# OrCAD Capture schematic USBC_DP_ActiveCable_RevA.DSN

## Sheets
1 P1_RevisionNote: title: Type-C to DP Active Cable Board; rev: A.0; company: Texas Instruments, CIS/ICP
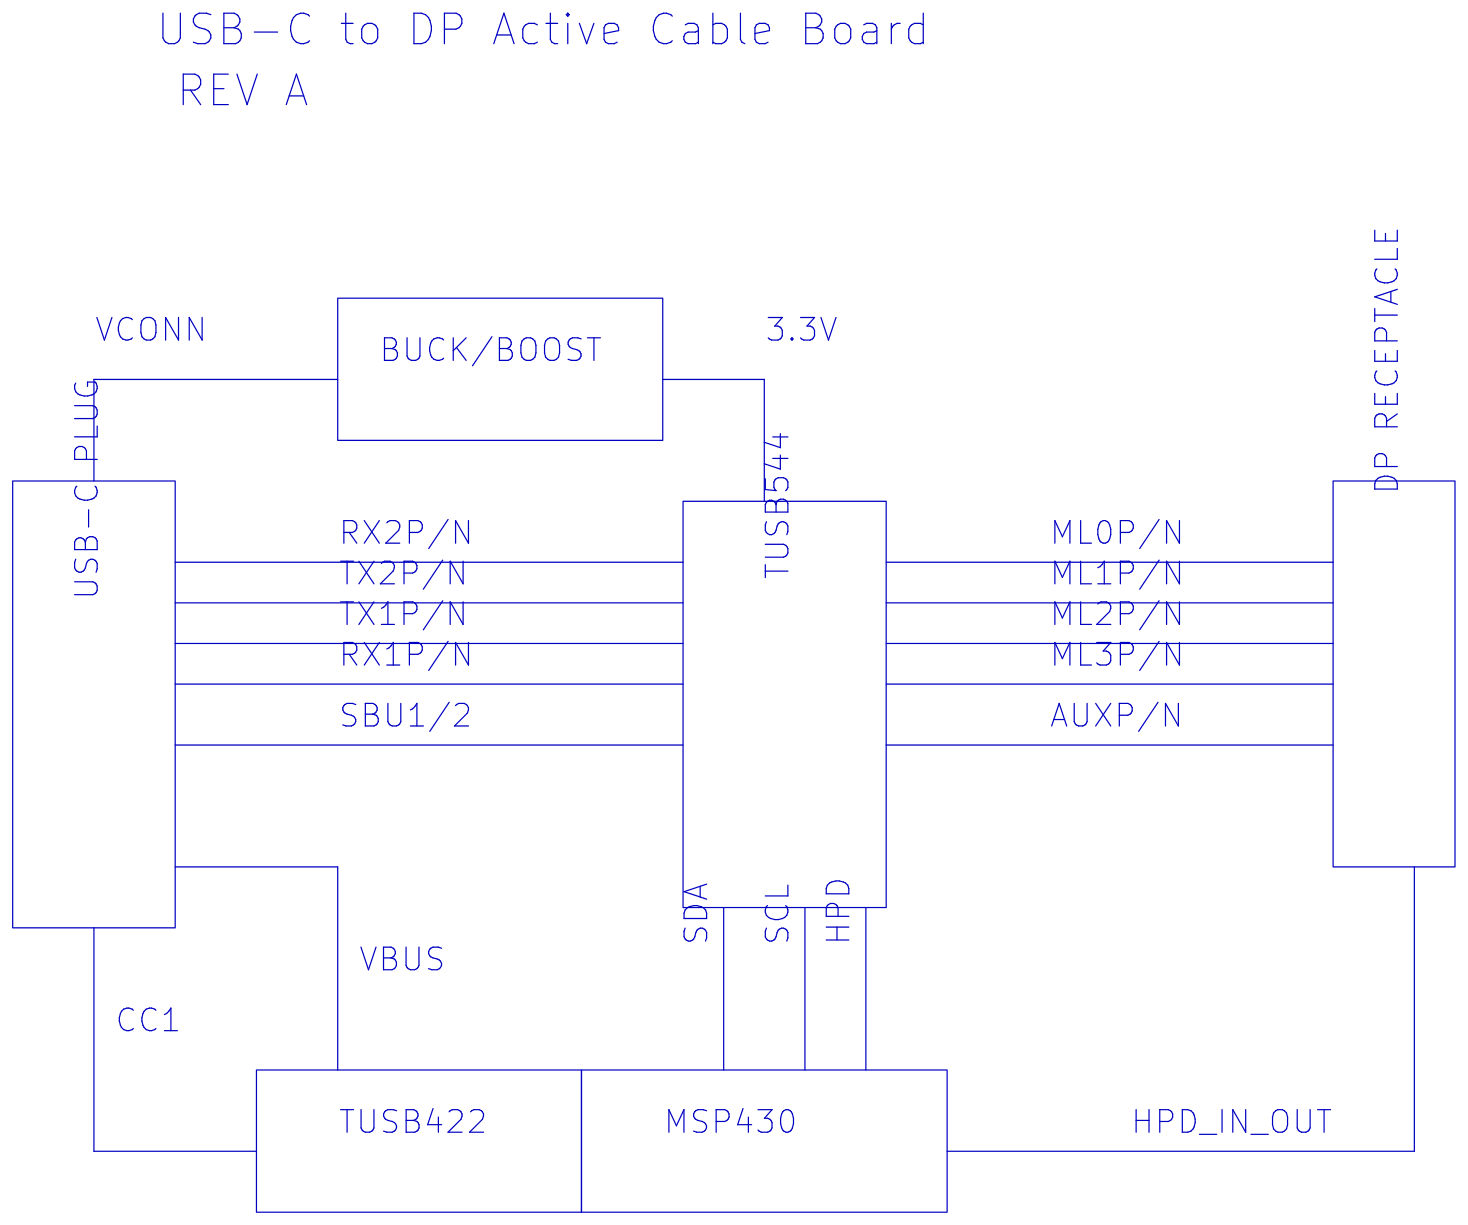
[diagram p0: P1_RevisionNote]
2 P2_TypeC_DP_Connectors: size C; title: USB-C DP ActiveCable Board: USB Connectors
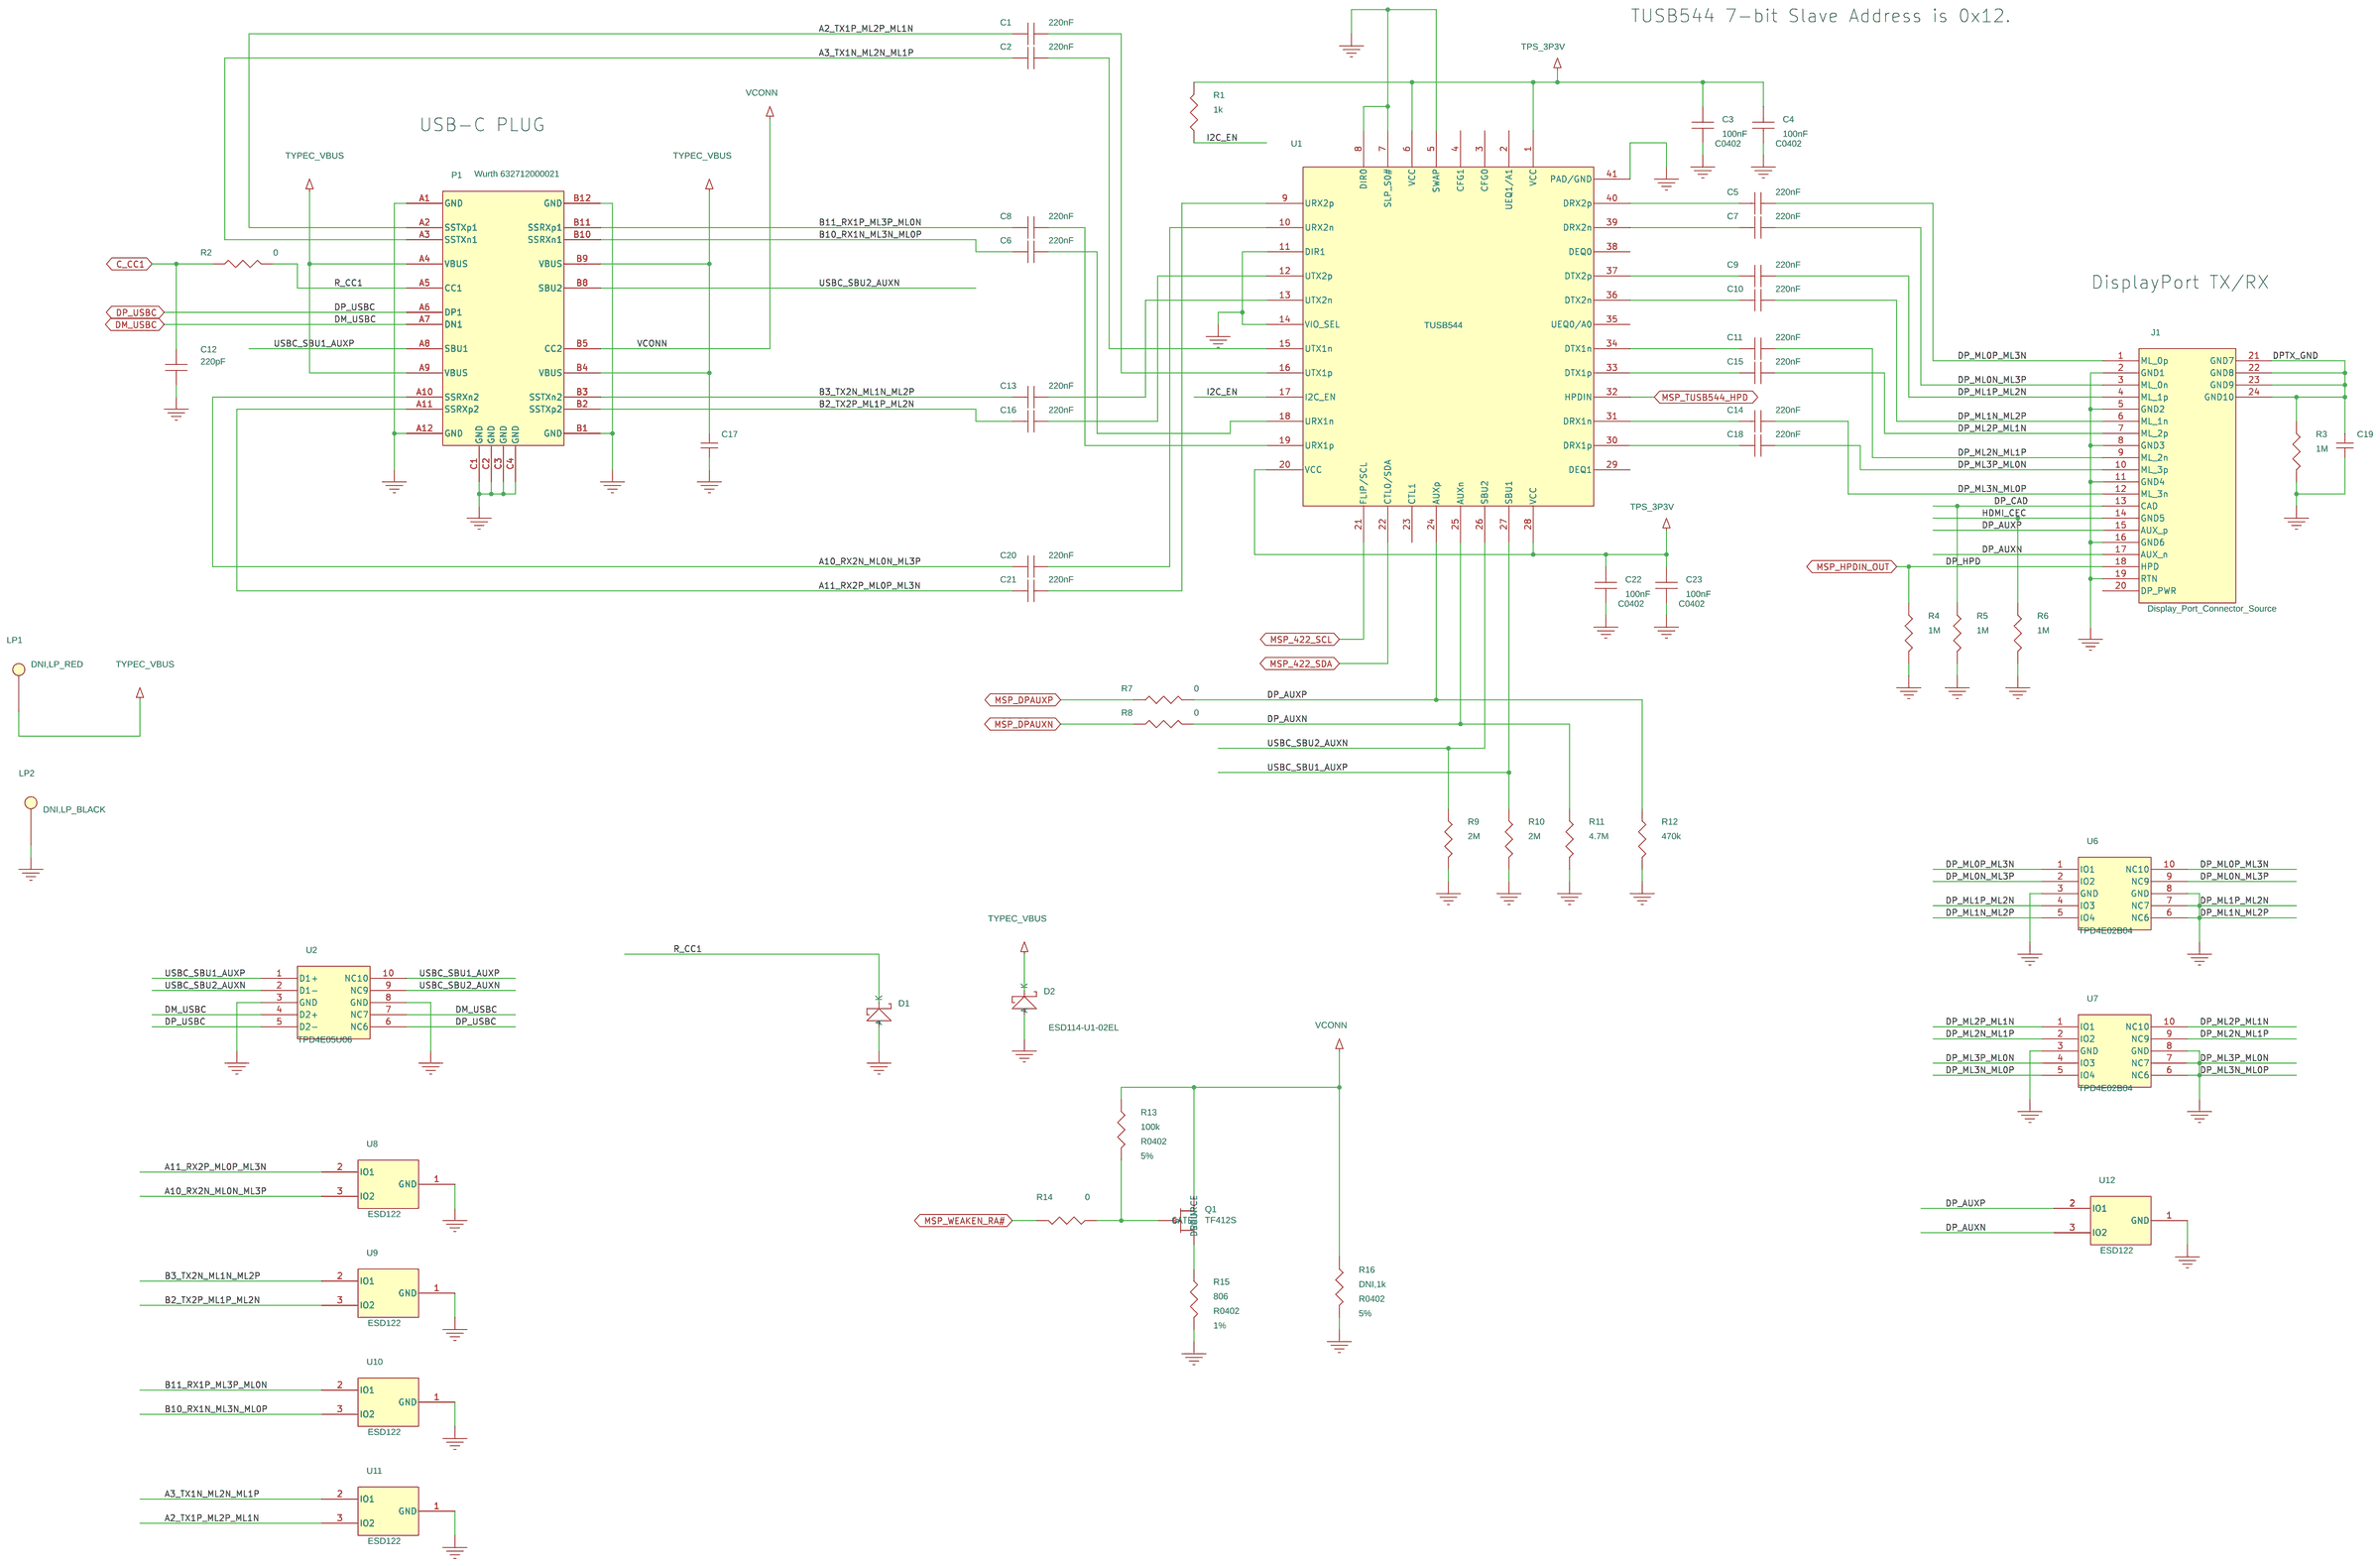
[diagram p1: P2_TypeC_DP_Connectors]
3 P3_TUSB422: size A; title: USB-C DP Active Cable Board: TUSB422
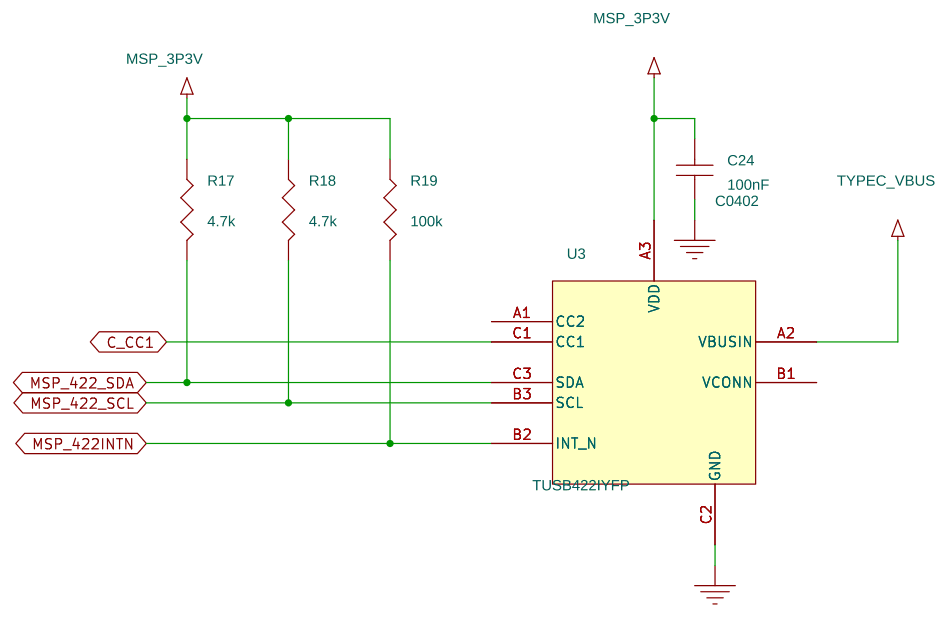
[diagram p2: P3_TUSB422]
4 P4_MSP430: size B; title: USB-C DP Active Cable Board: MSP430F5528
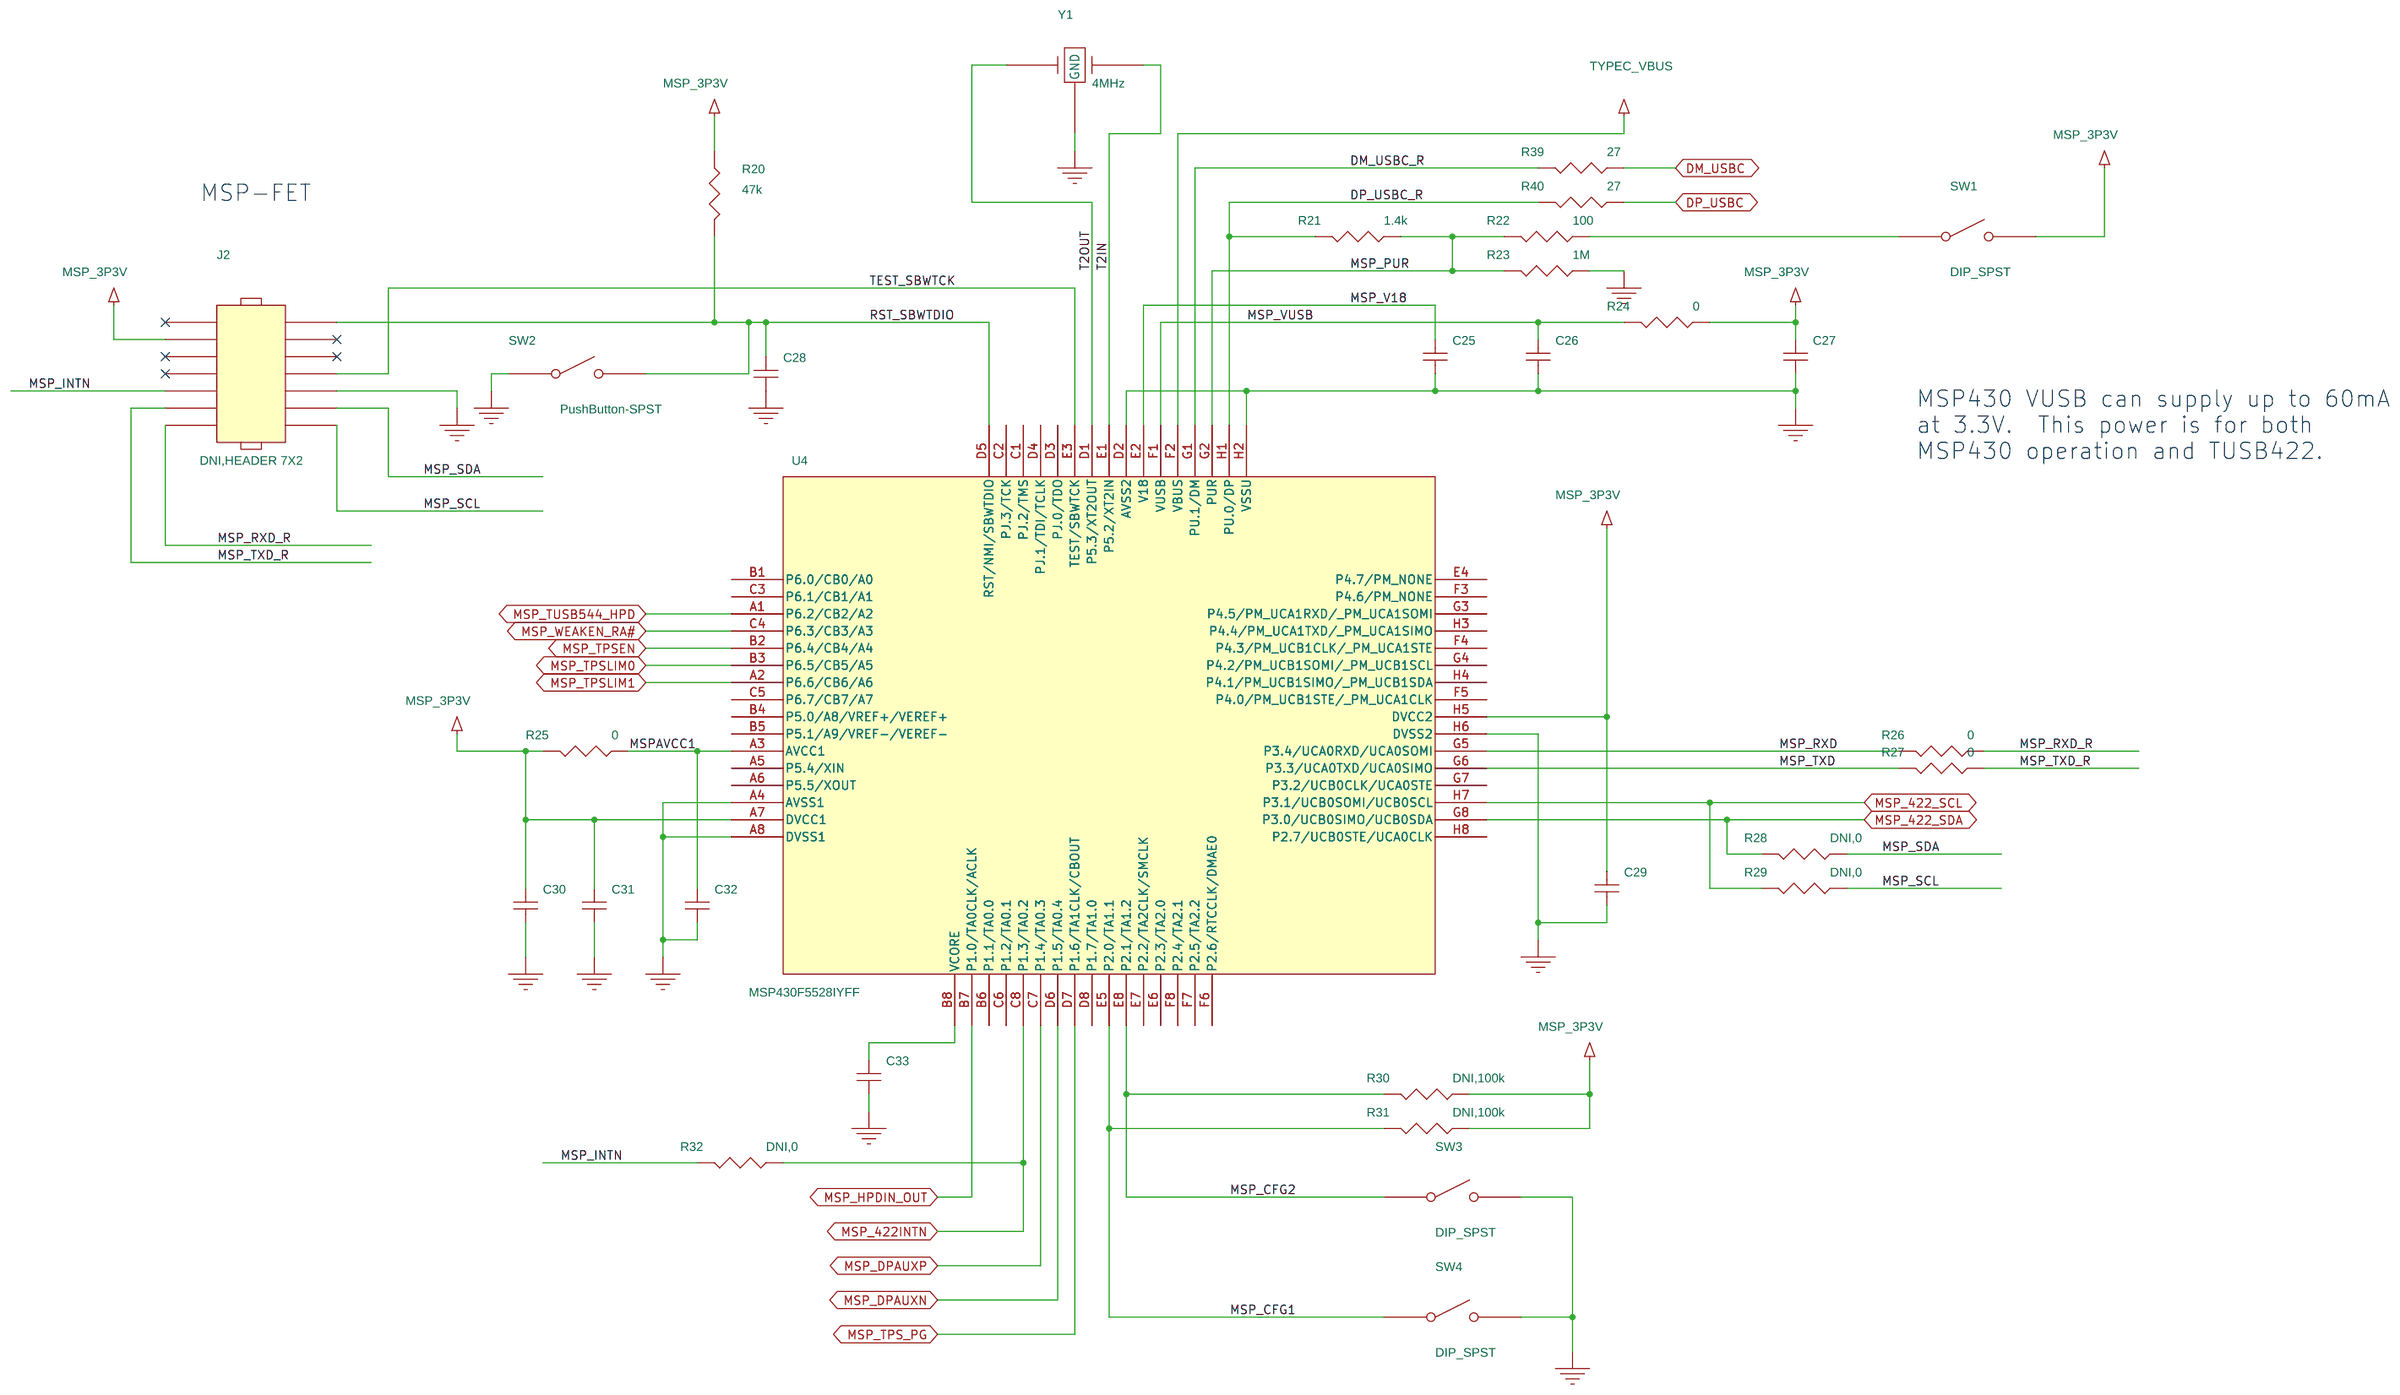
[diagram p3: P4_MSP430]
5 P5_POWER: size A; title: USB-C DP Active Cable Board: TPS63051
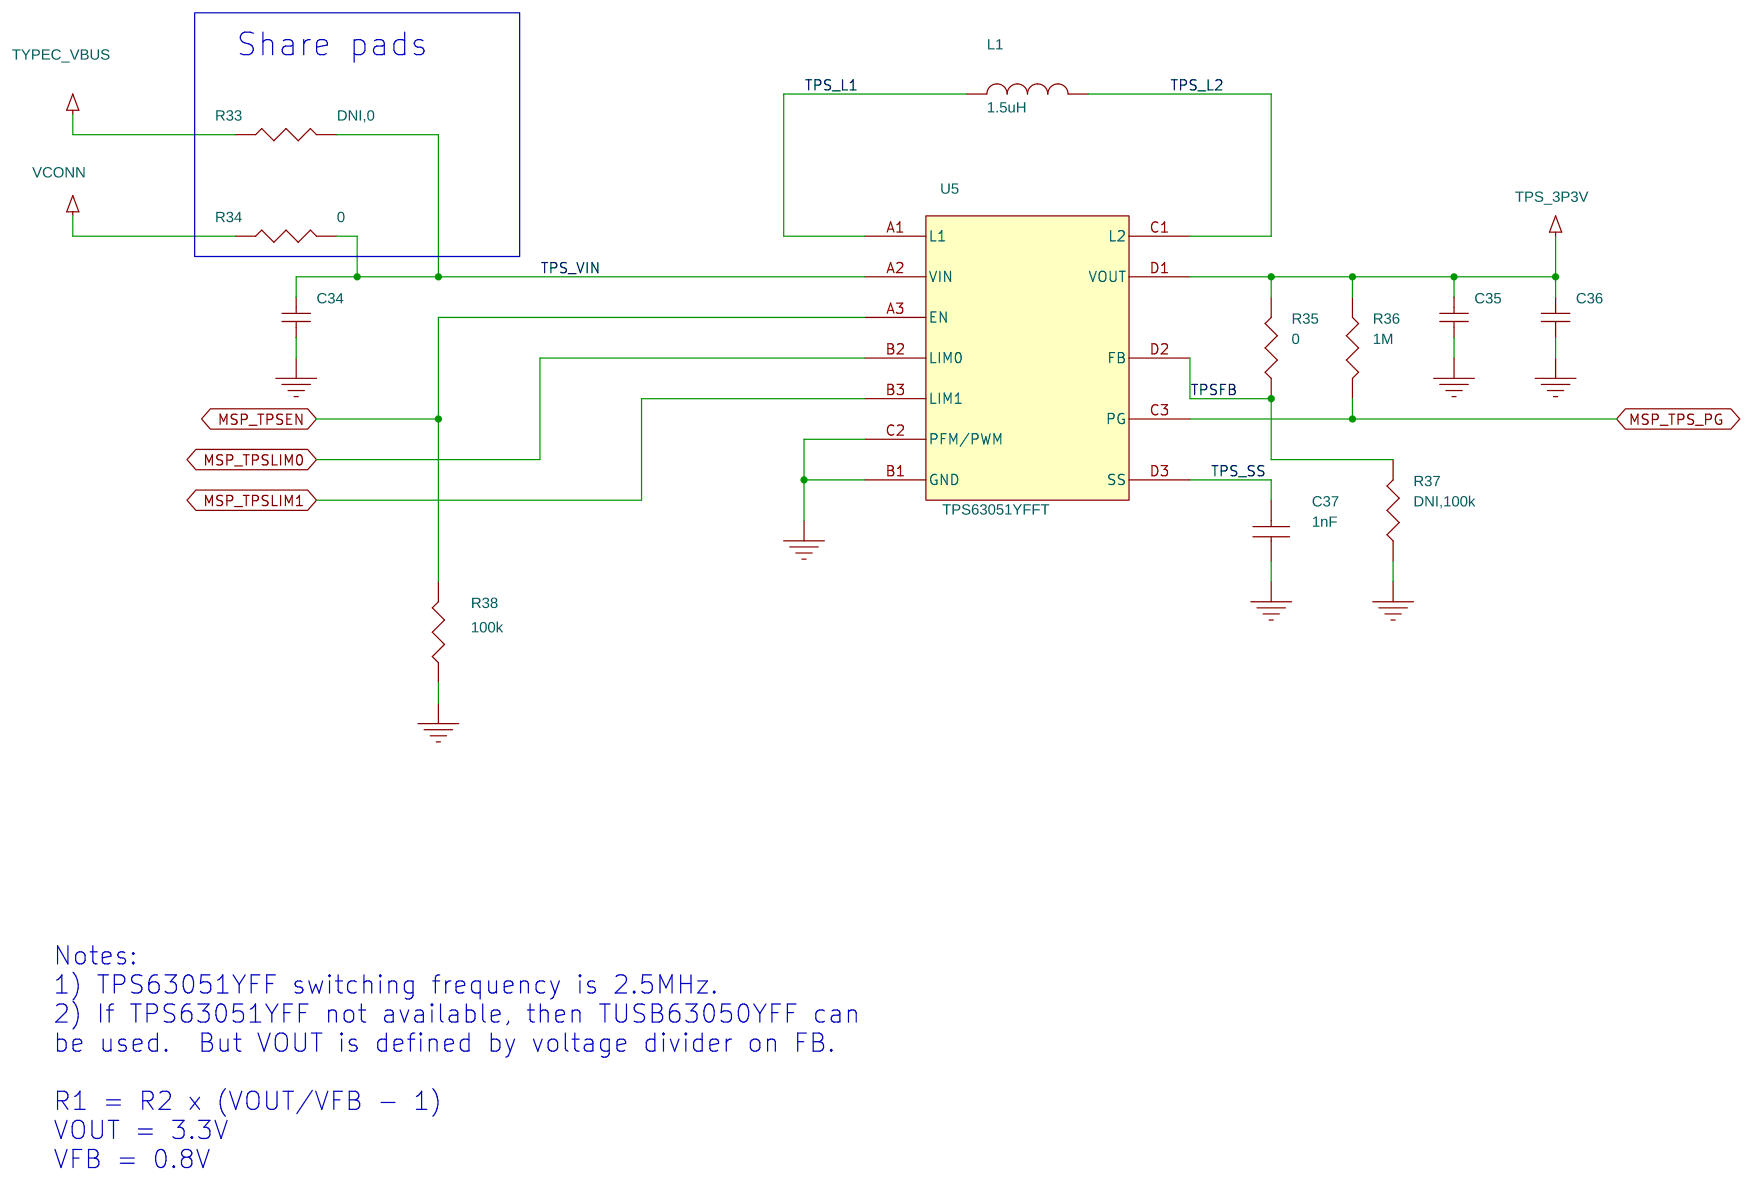
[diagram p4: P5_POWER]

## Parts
sheet P2_TypeC_DP_Connectors
C1  220nF  [C0402]
C2  220nF  [C0402]
C3  100nF  [C0402]
C4  100nF  [C0402]
C5  220nF  [C0402]
C6  220nF  [C0402]
C7  220nF  [C0402]
C8  220nF  [C0402]
C9  220nF  [C0402]
C10  220nF  [C0402]
C11  220nF  [C0402]
C12  220pF  [C0402]
C13  220nF  [C0402]
C14  220nF  [C0402]
C15  220nF  [C0402]
C16  220nF  [C0402]
C17  4.7uF  [C0402]
C18  220nF  [C0402]
C19  1uF  [C0402]
C20  220nF  [C0402]
C21  220nF  [C0402]
C22  100nF  [C0402]
C23  100nF  [C0402]
D1  TPD1E05U06  [DPY0002AA]
D2  ESD114-U1-02EL  [sod_882]
J1  Display_Port_Connector_Source  [CON_DP_SD-47272-001]
LP1  DNI,LP_RED  [tp_thvt_060_rnd]
LP2  DNI,LP_BLACK  [tp_thvt_060_rnd]
P1  Wurth 632712000021  [USB-C_SMRT_632_712_000_021]
Q1  TF412S  [SOT-883]
R1  1k  [R0402]
R2  0  [R0402]
R3  1M  [R0402]
R4  1M  [R0402]
R5  1M  [R0402]
R6  1M  [R0402]
R7  0  [R0402]
R8  0  [R0402]
R9  2M  [R0402]
R10  2M  [R0402]
R11  4.7M  [R0402]
R12  470k  [R0402]
R13  100k  [R0402]
R14  0  [R0402]
R15  806  [R0402]
R16  DNI,1k  [R0402]
U1  TUSB544  [RNQ0040A]
U2  TPD4E05U06  [DQA0010A]
U6  TPD4E02B04  [DQA]
U7  TPD4E02B04  [DQA]
U8  ESD122  [DMX0003A]
U9  ESD122  [DMX0003A]
U10  ESD122  [DMX0003A]
U11  ESD122  [DMX0003A]
U12  ESD122  [DMX0003A]
sheet P3_TUSB422
C24  100nF  [C0402]
R17  4.7k  [R0402]
R18  4.7k  [R0402]
R19  100k  [R0402]
U3  TUSB422IYFP  [YFP_BGA_9]
sheet P4_MSP430
C25  220nF  [C0402]
C26  220nF  [C0402]
C27  1uF  [C0402]
C28  1nF  [C0402]
C29  100nF  [C0402]
C30  1uF  [C0402]
C31  100nF  [C0402]
C32  100nF  [C0402]
C33  470nF  [C0402]
J2  DNI,HEADER 7X2  [HDR_THVT_2x7_100_M]
R20  47k  [R0402]
R21  1.4k  [R0402]
R22  100  [R0402]
R23  1M  [R0402]
R24  0  [R0402]
R25  0  [R0402]
R26  0  [R0402]
R27  0  [R0402]
R28  DNI,0  [R0402]
R29  DNI,0  [R0402]
R30  DNI,100k  [R0402]
R31  DNI,100k  [R0402]
R32  DNI,0  [R0402]
R39  27  [R0402]
R40  27  [R0402]
SW1  DIP_SPST  [SW_SMVT_CHS-01TA]
SW2  PushButton-SPST  [SW_SMVT_KXT]
SW3  DIP_SPST  [SW_SMVT_CHS-01TA]
SW4  DIP_SPST  [SW_SMVT_CHS-01TA]
U4  MSP430F5528IYFF  [YFF0064A]
Y1  4MHz  [XTAL_SM_3_CSTCR_G15L]
sheet P5_POWER
C34  10uF  [C0603]
C35  10uF  [C0402]
C36  10uF  [C0402]
C37  1nF  [C0402]
L1  1.5uH  [IND_DFE2016C]
R33  DNI,0  [R0603]
R34  0  [R0603]
R35  0  [R0402]
R36  1M  [R0402]
R37  DNI,100k  [R0402]
R38  100k  [R0402]
U5  TPS63051YFFT  [YFF0012A]

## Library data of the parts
C1 C2 C5-C16 C18 C20 C21 C37 = cc0402: 6.3V
C3 C4 C22-C24 = CAP_NP: 10V Capacitor
C17 C19 C25-C36 = CAP: 10V Capacitor; $SEC: 1; ATIPartNo: 4170010400G; CDS_LIB: capacitor; DRAWING: @LIGHTNING_BOLT_NB_LIB.NOTE_BOOK(SCH_1):PAGE1; PHYS_PAGE: 1; ROT: 0; TOLERANCE: 10%; VER: 1; VOLTAGE: 10V; XY: (-8750,4250)
D1 = TPD1E05U06
D2 = TPD1E05U06: Manuf: Infineon Tech; Manuf PN: ESD114U102ELE6327XTMA1
J1 = Display_Port_Connector_Source_0: Manuf: Molex; Manuf PN: 47272-0001
LP1 = TESTLOOP: Manufacturer: KOBIKONN; Manufacturer Part Number: 151-107-RC
LP2 = TESTLOOP: Manufacturer: KOBIKONN; Manufacturer Part Number: 151-105-RC
P1 = Type_C_Plug_0: Manuf: Wurth Electronics; Manuf PN: 632712000021; Manufacturer: Wurth Electronics; Manufacturer Part Number: 632712000021
Q1 = TF412S
R1 R13 R14 R16 = R: Resistor; Tolerance: 5%
R2 R7 R8 R33-R35 R37 R38 = R: Tolerance: 5%
R3-R6 R9-R12 R17-R32 R36 R39 R40 = R_2: Resistor; Tolerance: 5%
R15 = R: Resistor; Tolerance: 1%
U1 = TUSB1044RNQ: Manuf: Texas Instruments; Manuf PN: TUSB544RNQR
U2 = TPD4E05U06: Manuf: Texas Instruments
U6 U7 = TPD4E02B04: Manuf PN: TPD4E02B04DQAR
U8-U12 = ESD122
U3 = TUSB422_WCSP: Manuf: Texas Instruments; Manuf PN: TUSB422IYFPT; Manufacturer Part Number: TUSB422IYFPT
J2 = HEADER_7X2: Header; Manuf: Amphenol FCI; Manuf PN: 67996-114HLF; TI_SILKSCREEN: MSP430_SERIAL_WIRE
SW1 SW3 SW4 = SW_MAG-SPST: Manuf: Copal Electronics; Manuf PN: CHS-01TA
SW2 = SW_MAG-SPST: Manuf: C&K; Manuf PN: KXT 131 LHS
U4 = MSP430F5528IYFF_1: Manuf: Texas Instruments; Manuf PN: MSP430F5528IYFFR
Y1 = XM_SM_0: Manuf: Murata; Manuf PN: CSTCR4M00G15L99-R0
L1 = INDUCTOR: Inductor; CDS_LIB: Inductor; Manuf: TOKO; Manuf PN: 1286AS-H-1R5M; Manufacturer: TOKO; Manufacturer Part Number: 1286AS-H-1R5M; Manufacturer's Part Number: 1286AS-H-1R5M
U5 = TPS63051YFFT: Manuf: Texas Instruments

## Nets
GND: C3.1 C4.1 C12.1 C17.2(B) C19.2(B) C22.1 C23.1 C24.1 C25.2(B) C26.2(B) C27.2(B) C28.2(B) C29.2(B) C30.2(B) C31.2(B) C32.2(B) C33.2(B) C34.2(B) C35.2(B) C36.2(B) C37.1 D1.2(A) D2.2(A) J1.2(GND1) J1.5(GND2) J1.8(GND3) J1.11(GND4) J1.16(GND6) J1.19(RTN) J2.9 LP2.1 P1.A1(GND) P1.A12(GND) P1.B1(GND) P1.B12(GND) P1.C1(GND) P1.C2(GND) P1.C3(GND) P1.C4(GND) R3.2 R4.2 R5.2 R6.2 R9.2 R10.2 R11.2 R12.2 R15.2 R16.2 R23.1 R37.1 R38.1 SW2.1 SW3.2 SW4.2 U1.5(SWAP) U1.7(SLP_S0#) U1.8(DIR0) U1.11(DIR1) U1.14(VIO_SEL) U1.41(PAD/GND) U2.3(GND) U2.8(GND) U3.C2(GND) U4.A4(AVSS1) U4.A8(DVSS1) U4.D2(AVSS2) U4.H2(VSSU) U4.H6(DVSS2) U5.B1(GND) U5.C2(PFM/PWM) U6.3(GND) U6.8(GND) U7.3(GND) U7.8(GND) U8.1(GND) U9.1(GND) U10.1(GND) U11.1(GND) U12.1(GND) Y1.2(GND)
A2_TX1P_ML2P_ML1N: C1.2 P1.A2(SSTXp1) U11.3(IO2)
A3_TX1N_ML2N_ML1P: C2.2 P1.A3(SSTXn1) U11.2(IO1)
A10_RX2N_ML0N_ML3P: C20.2 P1.A10(SSRXn2) U8.3(IO2)
A11_RX2P_ML0P_ML3N: C21.2 P1.A11(SSRXp2) U8.2(IO1)
B2_TX2P_ML1P_ML2N: C16.2 P1.B2(SSTXp2) U9.3(IO2)
B3_TX2N_ML1N_ML2P: C13.2 P1.B3(SSTXn2) U9.2(IO1)
B10_RX1N_ML3N_ML0P: C6.2 P1.B10(SSRXn1) U10.3(IO2)
B11_RX1P_ML3P_ML0N: C8.2 P1.B11(SSRXp1) U10.2(IO1)
C_CC1: C12.2 R2.1 U3.C1(CC1)
DM_USBC: P1.A7(DN1) R39.1 U2.4(D2+) U2.7(NC7)
DM_USBC_R: R39.2 U4.G1(PU.1/DM)
DP_AUXN: J1.17(AUX_n) R8.2 R11.1 U1.25(AUXn) U12.3(IO2)
DP_AUXP: J1.15(AUX_p) R7.2 R12.1 U1.24(AUXp) U12.2(IO1)
DP_CAD: J1.13(CAD) R5.1
DP_ML0N_ML3P: C7.1 J1.3(ML_0n) U6.2(IO2) U6.9(NC9)
DP_ML0P_ML3N: C5.1 J1.1(ML_0p) U6.1(IO1) U6.10(NC10)
DP_ML1N_ML2P: C10.1 J1.6(ML_1n) U6.5(IO4) U6.6(NC6)
DP_ML1P_ML2N: C9.1 J1.4(ML_1p) U6.4(IO3) U6.7(NC7)
DP_ML2N_ML1P: C11.1 J1.9(ML_2n) U7.2(IO2) U7.9(NC9)
DP_ML2P_ML1N: C15.1 J1.7(ML_2p) U7.1(IO1) U7.10(NC10)
DP_ML3N_ML0P: C14.1 J1.12(ML_3n) U7.5(IO4) U7.6(NC6)
DP_ML3P_ML0N: C18.1 J1.10(ML_3p) U7.4(IO3) U7.7(NC7)
DP_USBC: P1.A6(DP1) R40.1 U2.5(D2-) U2.6(NC6)
DP_USBC_R: R21.2 R40.2 U4.H1(PU.0/DP)
DPTX_GND: C19.1(A) J1.21(GND7) J1.22(GND8) J1.23(GND9) J1.24(GND10) R3.1
HDMI_CEC: J1.14(GND5) R6.1
I2C_EN: R1.1 U1.17(I2C_EN)
MSP_3P3V: C24.2 C27.1(A) C29.1(A) C30.1(A) C31.1(A) J2.4 R17.1 R18.1 R19.1 R20.1 R24.1 R25.2 R30.1 R31.1 SW1.2 U3.A3(VDD) U4.A7(DVCC1) U4.H5(DVCC2)
MSP_422_SCL: R18.2 R29.2 U1.21(FLIP/SCL) U3.B3(SCL) U4.H7(P3.1/UCB0SOMI/UCB0SCL)
MSP_422_SDA: R17.2 R28.2 U1.22(CTL0/SDA) U3.C3(SDA) U4.G8(P3.0/UCB0SIMO/UCB0SDA)
MSP_422INTN: R19.2 R32.1 U3.B2(INT_N) U4.C8(P1.3/TA0.2)
MSP_CFG1: R31.2 SW4.1 U4.E5(P2.0/TA1.1)
MSP_CFG2: R30.2 SW3.1 U4.E8(P2.1/TA1.2)
MSP_DPAUXN: R8.1 U4.D6(P1.5/TA0.4)
MSP_DPAUXP: R7.1 U4.C7(P1.4/TA0.3)
MSP_HPDIN_OUT: J1.18(HPD) R4.1 U4.B7(P1.0/TA0CLK/ACLK)
MSP_INTN: J2.10 R32.2
MSP_PUR: R21.1 R22.2 R23.2 U4.G2(PUR)
MSP_RXD: R26.2 U4.G5(P3.4/UCA0RXD/UCA0SOMI)
MSP_RXD_R: J2.14 R26.1
MSP_SCL: J2.13 R29.1
MSP_SDA: J2.11 R28.1
MSP_TPS_PG: R36.2 U4.D7(P1.6/TA1CLK/CBOUT) U5.C3(PG)
MSP_TPSEN: R38.2 U4.B2(P6.4/CB4/A4) U5.A3(EN)
MSP_TPSLIM0: U4.B3(P6.5/CB5/A5) U5.B2(LIM0)
MSP_TPSLIM1: U4.A2(P6.6/CB6/A6) U5.B3(LIM1)
MSP_TUSB544_HPD: U1.32(HPDIN) U4.A1(P6.2/CB2/A2)
MSP_TXD: R27.2 U4.G6(P3.3/UCA0TXD/UCA0SIMO)
MSP_TXD_R: J2.12 R27.1
MSP_V18: C25.1(A) U4.E2(V18)
MSP_VUSB: C26.1(A) R24.2 U4.F1(VUSB)
MSP_WEAKEN_RA#: R14.1 U4.C4(P6.3/CB3/A3)
MSPAVCC1: C32.1(A) R25.1 U4.A3(AVCC1)
R_CC1: D1.1(K) P1.A5(CC1) R2.2
RST_SBWTDIO: C28.1(A) J2.1 R20.2 SW2.2 U4.D5(RST/NMI/SBWTDIO)
T2IN: U4.E1(P5.2/XT2IN) Y1.3
T2OUT: U4.D1(P5.3/XT2OUT) Y1.1
TEST_SBWTCK: J2.7 U4.E3(TEST/SBWTCK)
TPS_3P3V: C3.2 C4.2 C22.2 C23.2 C35.1(A) C36.1(A) R1.2 R35.2 R36.1 U1.1(VCC) U1.6(VCC) U1.20(VCC) U1.28(VCC) U5.D1(VOUT)
TPS_L1: L1.1 U5.A1(L1)
TPS_L2: L1.2 U5.C1(L2)
TPS_SS: C37.2 U5.D3(SS)
TPS_VIN: C34.1(A) R33.2 R34.2 U5.A2(VIN)
TPSFB: R35.1 R37.2 U5.D2(FB)
TypeC_VBUS: C17.1(A) D2.1(K) LP1.1 P1.A4(VBUS) P1.A9(VBUS) P1.B4(VBUS) P1.B9(VBUS) R33.1 U3.A2(VBUSIN) U4.F2(VBUS)
USBC_SBU1_AUXP: P1.A8(SBU1) R10.1 U1.27(SBU1) U2.1(D1+) U2.10(NC10)
USBC_SBU2_AUXN: P1.B8(SBU2) R9.1 U1.26(SBU2) U2.2(D1-) U2.9(NC9)
VCONN: P1.B5(CC2) Q1.2(DRAIN) R13.1 R16.1 R34.1
N17347753: C33.1(A) U4.B8(VCORE)
N17354680: R22.1 SW1.1
N17413185: C5.2 U1.40(DRX2p)
N17413188: C7.2 U1.39(DRX2n)
N17413191: C9.2 U1.37(DTX2p)
N17413194: C10.2 U1.36(DTX2n)
N17413197: C11.2 U1.34(DTX1n)
N17413200: C15.2 U1.33(DTX1p)
N17413203: C14.2 U1.31(DRX1n)
N17413206: C18.2 U1.30(DRX1p)
N17415406: C21.1 U1.9(URX2p)
N17415415: C20.1 U1.10(URX2n)
N17415424: C16.1 U1.12(UTX2p)
N17415436: C13.1 U1.13(UTX2n)
N17415457: C8.1 U1.19(URX1p)
N17415476: C6.1 U1.18(URX1n)
N17415496: C2.1 U1.15(UTX1n)
N17415505: C1.1 U1.16(UTX1p)
N17425671: Q1.3(GATE) R13.2 R14.2
N17429646: Q1.1(SOURCE) R15.1

Not connected (* = marked no-connect by the designer): J1 20(DP_PWR); J2 2* 3* 5* 6* 8*; U1 2(UEQ1/A1) 3(CFG0) 4(CFG1) 23(CTL1) 29(DEQ1) 35(UEQ0/A0) 38(DEQ0); U3 A1(CC2) B1(VCONN); U4 A5(P5.4/XIN) A6(P5.5/XOUT) B1(P6.0/CB0/A0) B4(P5.0/A8/VREF+/VEREF+) B5(P5.1/A9/VREF-/VEREF-) B6(P1.1/TA0.0) C1(PJ.2/TMS) C2(PJ.3/TCK) C3(P6.1/CB1/A1) C5(P6.7/CB7/A7) C6(P1.2/TA0.1) D3(PJ.0/TDO) D4(PJ.1/TDI/TCLK) D8(P1.7/TA1.0) E4(P4.7/PM_NONE) E6(P2.3/TA2.0) E7(P2.2/TA2CLK/SMCLK) F3(P4.6/PM_NONE) F4(P4.3/PM_UCB1CLK/_PM_UCA1STE) F5(P4.0/PM_UCB1STE/_PM_UCA1CLK) F6(P2.6/RTCCLK/DMAE0) F7(P2.5/TA2.2) F8(P2.4/TA2.1) G3(P4.5/PM_UCA1RXD/_PM_UCA1SOMI) G4(P4.2/PM_UCB1SOMI/_PM_UCB1SCL) G7(P3.2/UCB0CLK/UCA0STE) H3(P4.4/PM_UCA1TXD/_PM_UCA1SIMO) H4(P4.1/PM_UCB1SIMO/_PM_UCB1SDA) H8(P2.7/UCB0STE/UCA0CLK)

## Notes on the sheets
sheet 1
- USB-C to DP Active Cable Board
- REV A
- VCONN
- 3.3V
- BUCK/BOOST
- DP RECEPTACLE
- RX2P/N
- ML0P/N
- TX2P/N
- ML1P/N
- TUSB544
- USB-C PLUG
- TX1P/N
- ML2P/N
- RX1P/N
- ML3P/N
- SBU1/2
- AUXP/N
- VBUS
- SDA
- SCL
- HPD
- CC1
- TUSB422
- MSP430
- HPD_IN_OUT
sheet 2
- TUSB544 7-bit Slave Address is 0x12.
- USB-C PLUG
- DisplayPort TX/RX
sheet 4
- MSP-FET
- MSP430 VUSB can supply up to 60mA
  at 3.3V.  This power is for both
  MSP430 operation and TUSB422.
sheet 5
- Share pads
- Notes:
  1) TPS63051YFF switching frequency is 2.5MHz.
  2) If TPS63051YFF not available, then TUSB63050YFF can
  be used.  But VOUT is defined by voltage divider on FB.
  R1 = R2 x (VOUT/VFB - 1)
  VOUT = 3.3V
  VFB = 0.8V
